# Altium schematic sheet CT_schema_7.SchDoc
size 372 x 245 mm
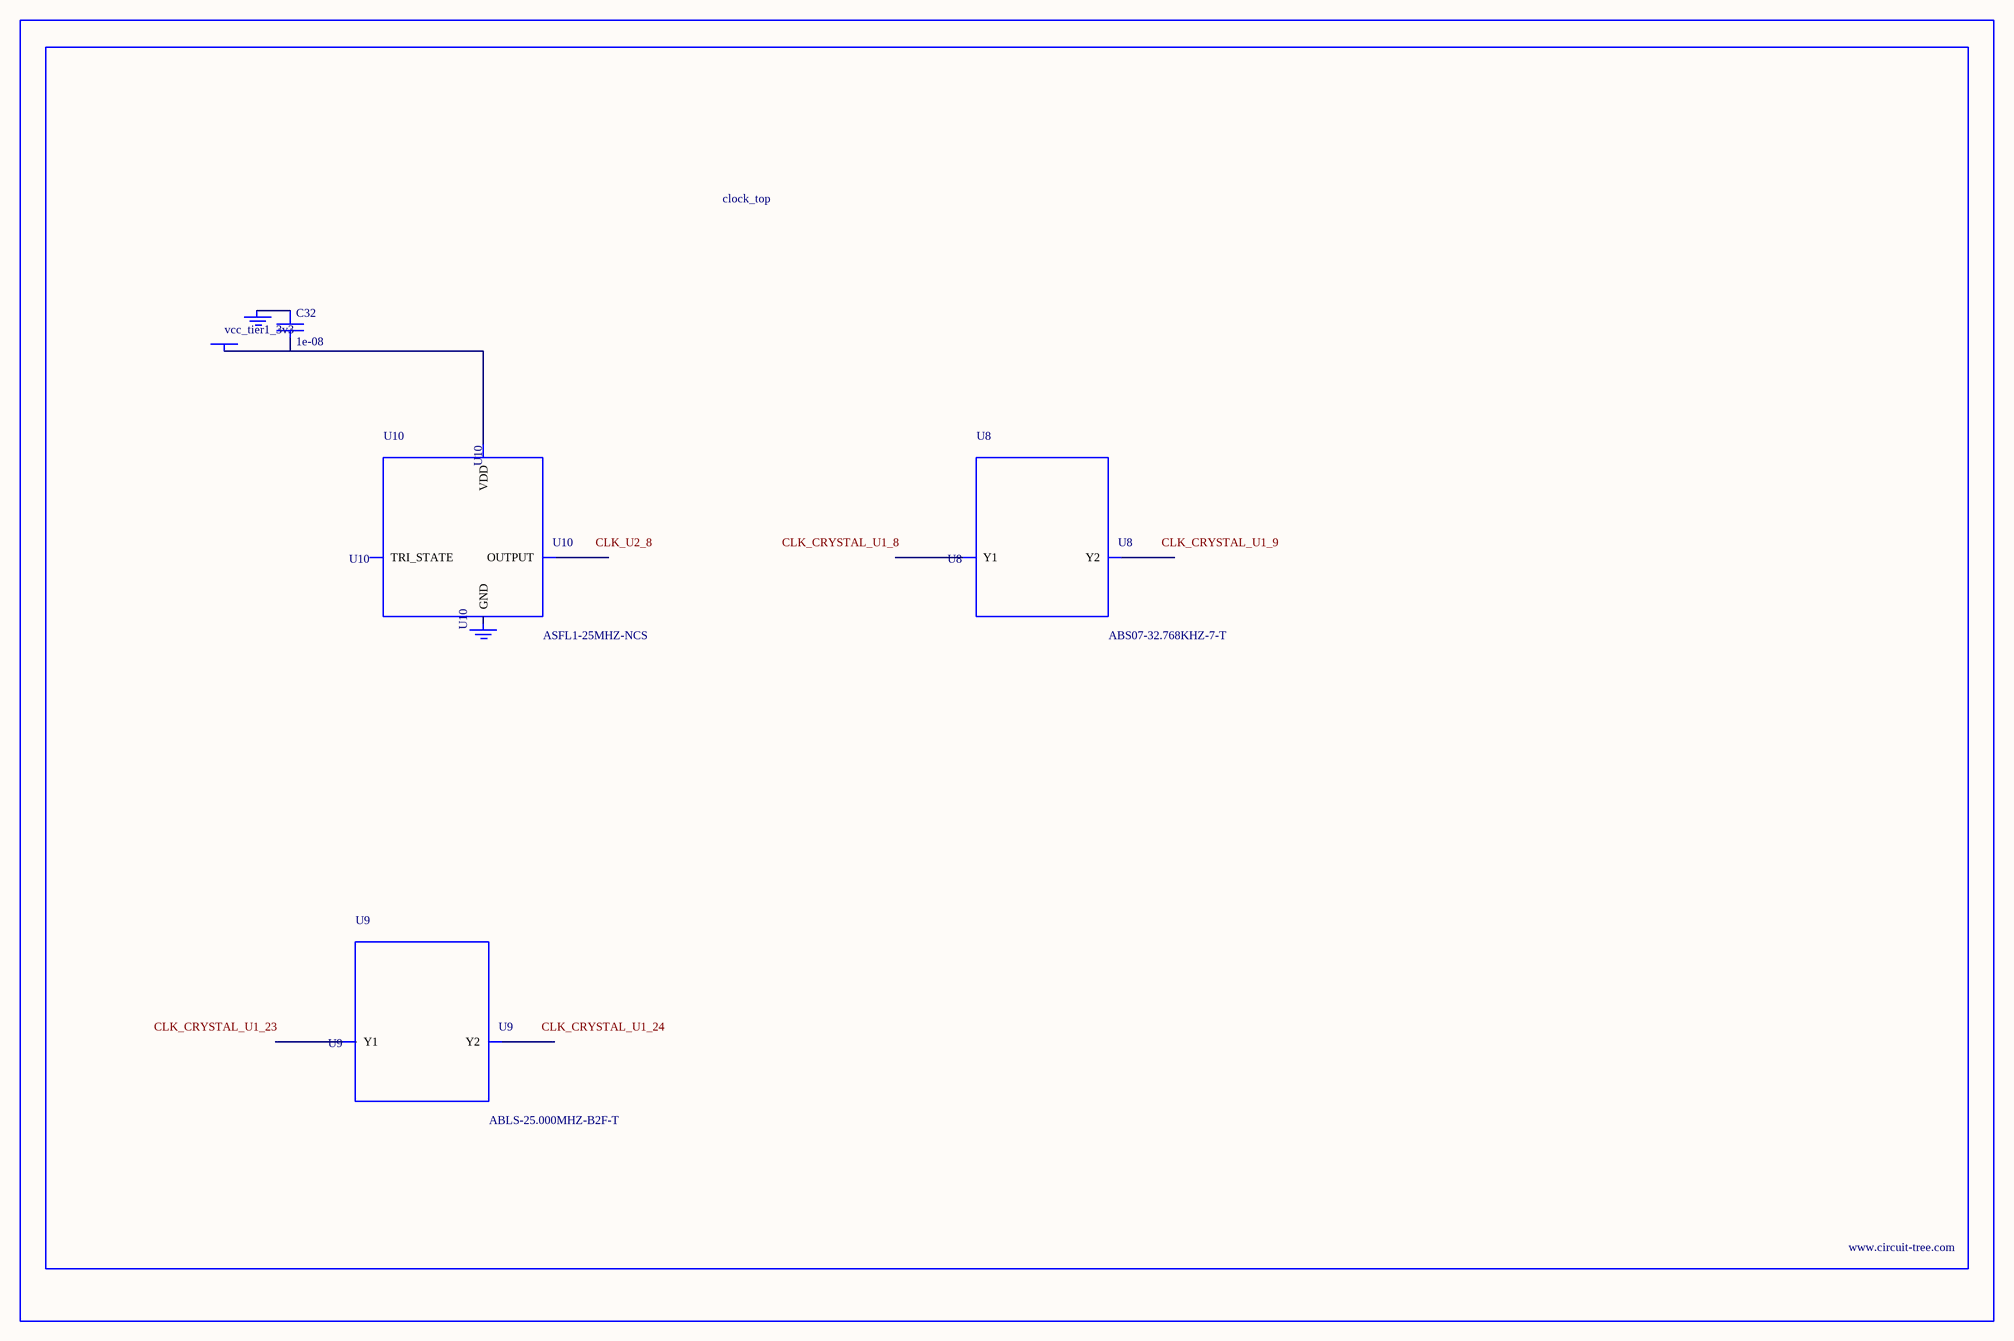
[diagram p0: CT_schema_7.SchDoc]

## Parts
BORDER6  (no value)
C32  1e-08  [C0402]
GND_INSTANCE_6_0  (no value)
GND_INSTANCE_6_1  (no value)
POWER_INSTANCE_6_0  vcc_tier1_3v3
U8  ABS07-32.768KHZ-7-T  [ABS07-32.768KHZ-7-T]
U9  ABLS-25.000MHZ-B2F-T  [ABLS-25.000MHZ-B2F-T]
U10  ASFL1-25MHZ-NCS  [ASFL1]

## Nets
NetC32_1: C32.1 GND_INSTANCE_6_0.0(GND)
NetC32_2: C32.2 POWER_INSTANCE_6_0.0(PWR) U10.4(VDD)

Not connected (* = marked no-connect by the designer): GND_INSTANCE_6_1 0(GND); U8 1(Y1) 2(Y2); U9 1(Y1) 2(Y2); U10 1(TRI_STATE) 2(GND) 3(OUTPUT)

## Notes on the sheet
- Labels drawn without touching a wire or pin: CLK_CRYSTAL_U1_8, CLK_CRYSTAL_U1_9, CLK_CRYSTAL_U1_23, CLK_CRYSTAL_U1_24, CLK_U2_8

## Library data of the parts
BORDER6 = BORDER_PAGE6
C32 = C0402C103K3RAC
GND_INSTANCE_6_0 GND_INSTANCE_6_1 = GND
POWER_INSTANCE_6_0 = PWR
